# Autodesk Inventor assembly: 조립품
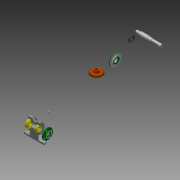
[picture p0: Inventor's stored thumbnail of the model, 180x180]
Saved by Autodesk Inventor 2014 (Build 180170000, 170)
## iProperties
Created: 2020-01
Part Number: 조립품
Document SubType Name: Assembly
Designer: kh
Author: kh
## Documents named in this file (13)
- C:\Users\kh\Desktop\700104V1033\조립품.iam
- C:\Users\kh\Desktop\700104V1033\본체.ipt
- C:\Users\kh\Desktop\700104V1033\Ű 5 x 5 x 18.ipt
- C:\Users\kh\Desktop\700104V1033\뒤커버.ipt
- C:\Users\kh\Desktop\700104V1033\멈춤나사 M3.ipt
- C:\Users\kh\Desktop\700104V1033\베어링 6203.ipt
- C:\Users\kh\Desktop\700104V1033\베어링 6205.ipt
- C:\Users\kh\Desktop\700104V1033\볼트 M4.ipt
- C:\Users\kh\Desktop\700104V1033\스퍼기어.ipt
- C:\Users\kh\Desktop\700104V1033\앞커버.ipt
- C:\Users\kh\Desktop\700104V1033\오일 실 17 30 8.ipt
- C:\Users\kh\Desktop\700104V1033\오일 실 25 38 8.ipt
- C:\Users\kh\Desktop\700104V1033\축.ipt
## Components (1 placed, 1 different names)
1. Ű 5 x 5 x 18:1
